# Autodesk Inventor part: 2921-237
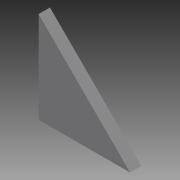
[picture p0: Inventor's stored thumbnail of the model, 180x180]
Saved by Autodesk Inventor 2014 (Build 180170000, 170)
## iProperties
Company: NHTSA/VRTC
Created: 2012-08
Part Number: 2921-237
Material: Steel, Mild
Document SubType Name: Modeling
Designer: Mike Vanvoorhis
Density: 7.86 g/cm^3
Mass: 64.4012 g
Surface Area: 36.82 cm^2
Volume: 8.19353 cm^3
Project: CHILD SIDE IMPACT SLED
Description: HONEYCOMB FRAME GUSSET PLATE
Stock Number: PL 6.4 (1/4") x 50.8 (2") x 50.8 (2")
Appearance: Steel
Author: Dave Walker
Title: Honeycomb Frame Gusset Plate
Subject: Child Side Impact Sled
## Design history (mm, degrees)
sketch "Sketch1"
  geometry: L1 (0, 0)-(50.8, 0); L2 (0, 0)-(0, 50.8); L3 (0, 50.8)-(50.8, 0)
  constraints: 6 end point, 1 horizontal, 1 perpendicular
  dimensions: "d0" = 50.8 distance of L1.start L1.end; "d1" = 50.8 distance of L1.start L2.end
extrude "Extrusion1" new body sketch "Sketch1" distance "d2" = 6.35; taper "d3" = 0 deg
body "Solid1"
